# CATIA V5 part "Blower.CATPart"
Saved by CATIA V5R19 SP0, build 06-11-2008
Part number: Blower
Bounding box of the stored display mesh (mm): x -139.7 to 139.7, y -139.7 to 139.7, z -63.5 to 184.15
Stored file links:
  C:\Users\CADCIM\Desktop\c12\Tutorial-1\Blower.CATPart
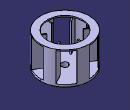
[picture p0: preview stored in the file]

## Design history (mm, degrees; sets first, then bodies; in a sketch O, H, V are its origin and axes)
Body1 (main body)
  Sketch1 on xy-plane, origin (0, 0, 0), H (1, 0, 0), V (0, 1, 0)
    circle A1 centre (0, 0) radius 139.7
    point P1 (0, 0)
    radius A1 = 139.7
    coincidence: P1 H, P1 O
  Pad1: profile Sketch1, direction (0, 0, 1), length 12.7
  Sketch2 on face of Pad1, origin (0, 0, 12.7), H (1, 0, 0), V (0, 1, 0)
    line L1 (0, 139.7) -> (0, 76.708)
    point P1 (0, 139.7)
    projected arc E1 centre (0, 0) radius 139.7 from (57.581, 127.2812) to (0, 139.7) ccw from edge of Pad1
    line L2 (6.35, 135.7416) -> (6.35, 76.708)
    arc A1 centre (0, 0) radius 135.89 from (55.7565, 123.9246) to (6.35, 135.7416) ccw
    line L3 (0, 76.708) -> (6.35, 76.708)
    line L4 (55.7565, 123.9246) -> (57.581, 127.2812)
    point P4 (55.7565, 123.9246)
    point P6 (6.35, 135.7416)
    length L1 = 62.992
    distance L1 L2 = 6.35
    distance E1 A1 = 3.81
    distance P6 P4 = 50.8
    coincidence: P1 V
    vertical: L1 V
    concentricity: E1 A1
    horizontal: L3 H
  Pad2: profile Sketch2, direction (0, 0, 1), length 165.1
  CircPattern1: of Pad2, instances 6, angular step 60, axis from edge of Sketch6
  Sketch3 on face of Pad1, origin (0, 0, 0), H (1, 0, 0), V (0, -1, 0)
    circle A1 centre (0, 0) radius 38.1
    radius A1 = 38.1
  Pad3: profile Sketch3, direction (0, 0, -1), length 63.5
  Sketch4 on face of Pad2, origin (0, 0, 177.8), H (1, 0, 0), V (0, 1, 0)
    circle A1 centre (0, 0) radius 139.7
    radius A1 = 139.7
  Pad4: profile Sketch4, direction (0, 0, 1), length 6.35
  Sketch5 on face of Pad4, origin (0, 0, 184.15), H (1, 0, 0), V (0, 1, 0)
    circle A1 centre (0, 0) radius 101.6
    circle A2 centre (0, 0) radius 19.05
    radius A2 = 19.05
    radius A1 = 101.6
  MultiPocket1: profile Sketch5, domains (length 381; length 6.35)
  Sketch6 on yz-plane, origin (0, 0, 0), H (0, 1, 0), V (0, 0, 1)
    line L1 (0, 3.7002) -> (0, 148.5199)
    point P1 (0, 3.7002)
    coincidence: P1 V
    vertical: L1 V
